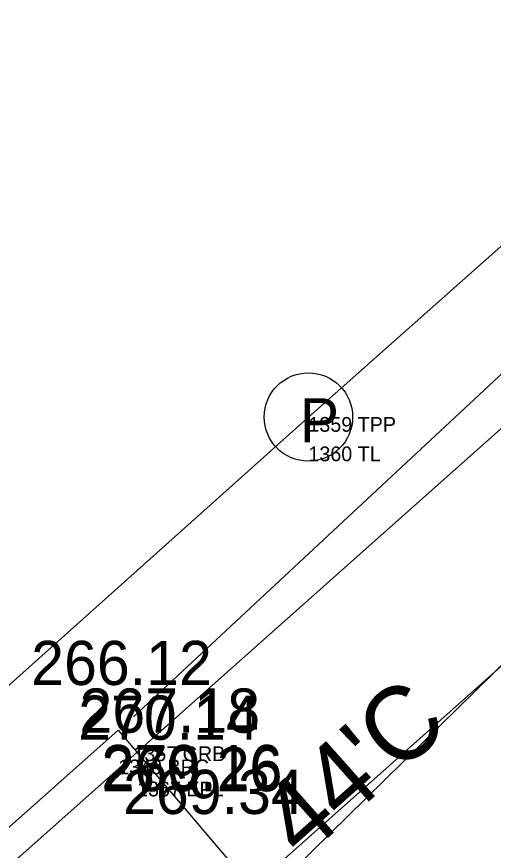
# Model space of a CAD drawing. Extents: x 49683 to 58852, y 49525 to 54803.
# Drawn here: x 53875.1 to 53907.5, y 51882.5 to 51939.1 of the extents above; entities that cross this region are included whole.
import ezdxf

# ---------------------------------------------------------------- set-up
doc = ezdxf.new("R2010")
doc.units = 0
for name, color, linetype in [('Level 1', 7, 'Continuous'), ('Level 11', 7, 'Continuous'), ('Level 18', 7, 'Continuous'), ('Level 3', 7, 'Continuous'), ('Level 32', 7, 'Continuous'), ('Level 48', 7, 'Continuous'), ('Level 5', 7, 'Continuous'), ('Level 53', 7, 'Continuous'), ('Level 55', 7, 'Continuous'), ('Level 57', 7, 'Continuous'), ('Level 59', 7, 'Continuous'), ('Level 61', 7, 'Continuous'), ('Level 7', 7, 'Continuous'), ('Level 9', 7, 'Continuous')]:
    doc.layers.add(name, color=color, linetype=linetype)

# ---------------------------------------------------------------- blocks, each defined once
blk = doc.blocks.new('TPP')
at = {"layer": 'Level 9'}
blk.add_circle((0, 0), 3, dxfattribs=at)
blk.add_text('P', height=3, dxfattribs=at).set_placement((-0.589, -1.729))

msp = doc.modelspace()

# ---------------------------------------------------------------- linework, layer by layer
at = {"layer": 'Level 1'}
msp.add_line((52544.807, 50683.302), (55534.583, 53340.862), dxfattribs=at)
at = {"layer": 'Level 11'}
for p, q in [((53894.91, 51911.927), (54324.203, 52292.615)), ((53424.495, 51490.929), (53894.91, 51911.927))]:
    msp.add_line(p, q, dxfattribs=at)
at = {"layer": 'Level 18'}
msp.add_line((53890.152, 51877.545), (53921.658, 51908.457), dxfattribs=at)
at = {"layer": 'Level 3'}
for p, q in [((53883.273, 51889.178), (54069.537, 52054.718)), ((53434.092, 51489.844), (53883.273, 51889.178))]:
    msp.add_line(p, q, dxfattribs=at)
at = {"layer": 'Level 5'}
for p, q in [((53432.563, 51491.203), (53881.993, 51890.68)), ((53881.993, 51890.68), (53900.074, 51869.402))]:
    msp.add_line(p, q, dxfattribs=at)
at = {"layer": 'Level 7'}
msp.add_line((53908.487, 51915.299), (53883.022, 51891.572), dxfattribs=at)

# ---------------------------------------------------------------- block references
at = {"layer": 'Level 9'}
msp.add_blockref('TPP', (53894.91, 51911.927), dxfattribs=at)

# ---------------------------------------------------------------- texts
at = {"layer": 'Level 32'}
for s, p in [('266.12', (53876.083, 51893.735)), ('267.18', (53879.362, 51890.501)), ('270.14', (53879.276, 51890.02)), ('270.16', (53880.858, 51886.67)), ('269.26', (53880.879, 51886.527)), ('269.34', (53882.324, 51884.982))]:
    msp.add_text(s, height=3, dxfattribs=at).set_placement(p)
at = {"layer": 'Level 48'}
msp.add_text("44'C", height=5, rotation=41.6334, dxfattribs=at).set_placement((53894.5, 51881.812))
at = {"layer": 'Level 53'}
msp.add_text('1367 EPL', height=1, dxfattribs=at).set_placement((53883.273, 51886.178))
at = {"layer": 'Level 55'}
msp.add_text('1349 BRC', height=1, dxfattribs=at).set_placement((53881.993, 51887.68))
at = {"layer": 'Level 57'}
msp.add_text('1357 GRB', height=1, dxfattribs=at).set_placement((53883.022, 51888.572))
at = {"layer": 'Level 59'}
msp.add_text('1359 TPP', height=1, dxfattribs=at).set_placement((53894.91, 51910.927))
at = {"layer": 'Level 61'}
msp.add_text('1360 TL', height=1, dxfattribs=at).set_placement((53894.91, 51908.927))

doc.saveas('drawing.dxf')
